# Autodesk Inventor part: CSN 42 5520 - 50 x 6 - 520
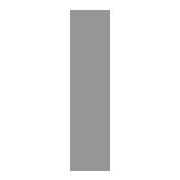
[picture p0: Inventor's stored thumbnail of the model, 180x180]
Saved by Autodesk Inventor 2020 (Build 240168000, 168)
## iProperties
IsCustomPart: 1
Created: 2019-01
Part Number: CSN 42 5520 - 50 x 6 - 520
Material: Ocel
Description: Tyč
Document SubType Name: Modeling
Standard: CSN 42 5520
Designer: doma
Standards Organization: CSN
Language: cs-CZ
Size Designation: 50 x 6 - 520
Categories: <MemberInstance><Categories><Category DisplayName="Konstrukční profily" InternalName="089c4875-fa83-4c05-b084-43b9cc11f5ed" Mnemonic="GRDR"><CategoryParameter D
Stock Number: 50 x 6
Density: 7.85 g/cm^3
Appearance: Plech
Mass: 1224.6 g
Surface Area: 588.4 cm^2
Volume: 156 cm^3
G_L: 520,000 mm
Author: doma
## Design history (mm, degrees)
node "Počáteční rovina"
node "Koncová rovina"
sketch "Náčrt"
  geometry: L1 (3, -25)-(-3, -25); L2 (-3, -25)-(-3, 25); L3 (-3, 25)-(3, 25); L4 (3, 25)-(3, -25); L5 (-6, 0)-(8, 0); L6 (0, -30)-(0, 40); L7 (0, 54)-(0, -44) reference; L8 (-9.2, 0)-(13.2, 0) reference
  constraints: 12 end point, 2 collinear, 2 parallel, 1 horizontal, 1 perpendicular
  dimensions: "d0" = 50 distance between parallel lines of L3 L1 (= G_W); "d1" = 6 distance between parallel lines of L4 L2 (= G_H); "d4" = 3 distance between parallel lines of L6 L4 (= 0.5 x d1); "d5" = 25 distance between parallel lines of L5 L3 (= 0.5 x d0)
extrude "Těleso" new body sketch "Náčrt" stored distance "d2" = 520 (= G_L); taper "d3" = 0 deg
node "Driven Length"
  sketch "Sketch3"
    geometry: L1 (0, 0)-(10, 0) reference
    constraints: 2 end point, 1 horizontal
  workplane "Work Plane3"
  sketch "Sketch4"
    geometry: L1 (-2, 0)-(12, 0) reference; L2 (-2, 520)-(12, 520) reference
    dimensions: "d9" = 520 distance between parallel lines of L1 L2 (derived)
node "Pracovní rovina4"
body "Solid1"
other parameters: "G_W" = 50 [user parameter; used in 1 equation term], "G_H" = 6 [user parameter; used in 1 equation term], "G_L" = 520 (= d9) [user parameter; used in 1 equation term], "G_OFFSET_START" = 0 [user parameter; used in 1 equation term], "G_OFFSET_END" = 0 [user parameter; used in 1 equation term], "d6" = 0 (computed from G_OFFSET_START), "d8" = 90 deg
